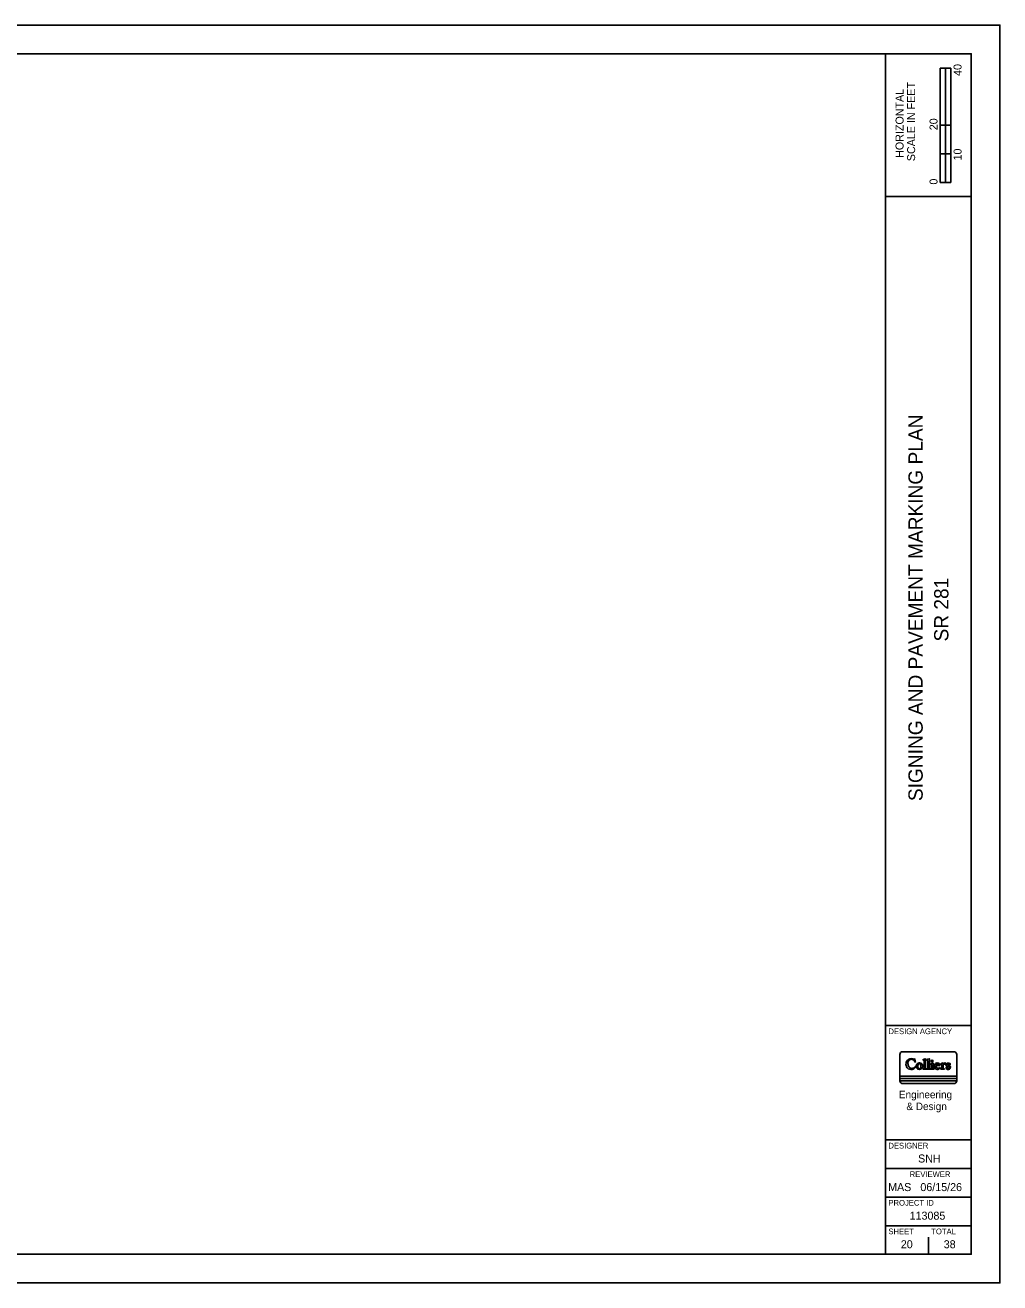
# Model space of a CAD drawing. Extents: x -0.1 to 34, y 0 to 22.
# Drawn here: x 16.94 to 34, y 0 to 22 of the extents above; entities that cross this region are included whole.
import ezdxf

# ---------------------------------------------------------------- set-up
doc = ezdxf.new("R2010")
doc.units = 0
for name, color, linetype in [('SH_Border', 7, 'Continuous'), ('SH_Cut_Line', 7, 'Continuous'), ('SH_Data', 7, 'Continuous'), ('SH_Text', 7, 'Continuous')]:
    doc.layers.add(name, color=color, linetype=linetype)

msp = doc.modelspace()

# ---------------------------------------------------------------- linework, layer by layer
at = {"layer": 'SH_Border'}
for p, q in [((32, 0.5), (32, 21.5)), ((32, 19), (33.5, 19)), ((32, 4.5), (33.5, 4.5)), ((32, 2.5), (33.5, 2.5)), ((32, 2), (33.5, 2)), ((32, 1.5), (33.5, 1.5)), ((32, 1), (33.5, 1))]:
    msp.add_line(p, q, dxfattribs=at)
msp.add_lwpolyline([(1.5, 21.5), (33.5, 21.5), (33.5, 0.5), (1.5, 0.5)], close=True, dxfattribs=at)
at = {"layer": 'SH_Cut_Line'}
msp.add_lwpolyline([(0, 0), (34, 0), (34, 22), (0, 22)], close=True, dxfattribs=at)
at = {"layer": 'SH_Data'}
for p, q in [((32.957, 19.25), (32.957, 21.25)), ((33.144, 21.25), (32.957, 21.25)), ((32.957, 20.25), (32.957, 21.25)), ((32.957, 21.25), (33.05, 21.25)), ((33.05, 21.25), (33.051, 21.25)), ((33.051, 21.25), (33.051, 20.25)), ((33.144, 21.25), (33.144, 19.25)), ((33.051, 20.25), (32.957, 20.25)), ((33.143, 20.25), (33.05, 20.25)), ((33.05, 20.25), (33.05, 19.75)), ((33.143, 19.75), (33.143, 20.25)), ((33.05, 19.75), (32.957, 19.75)), ((32.957, 19.75), (32.957, 19.25)), ((33.05, 19.25), (33.05, 19.75)), ((33.05, 19.75), (33.143, 19.75)), ((33.144, 19.25), (32.957, 19.25)), ((32.957, 19.25), (33.05, 19.25)), ((32.75, 3.5), (32.75, 3.5)), ((32.375, 0.675), (32.375, 0.675)), ((32.75, 0.5), (32.75, 0.8))]:
    msp.add_line(p, q, dxfattribs=at)
at = {"layer": 'SH_Text'}
for p, q in [((33.195, 4.043), (32.299, 4.043)), ((32.506, 3.913), (32.507, 3.91)), ((32.511, 3.864), (32.513, 3.859)), ((32.518, 3.765), (32.522, 3.77)), ((32.596, 3.846), (32.59, 3.846)), ((32.667, 3.745), (32.658, 3.745)), ((32.674, 3.881), (32.674, 3.753)), ((32.701, 3.752), (32.701, 3.916)), ((32.734, 3.745), (32.707, 3.745)), ((32.741, 3.879), (32.741, 3.751)), ((32.768, 3.751), (32.768, 3.916)), ((32.799, 3.745), (32.774, 3.745)), ((32.827, 3.846), (32.791, 3.832)), ((32.805, 3.812), (32.805, 3.751)), ((32.832, 3.749), (32.832, 3.843)), ((32.845, 3.745), (32.836, 3.745)), ((32.886, 3.802), (32.947, 3.802)), ((32.919, 3.81), (32.887, 3.81)), ((32.975, 3.745), (32.968, 3.745)), ((33, 3.846), (32.969, 3.831)), ((32.969, 3.825), (32.976, 3.821)), ((32.982, 3.81), (32.982, 3.753)), ((33.007, 3.828), (33.006, 3.843)), ((33.01, 3.753), (33.01, 3.807)), ((33.026, 3.745), (33.017, 3.745)), ((33.11, 3.833), (33.125, 3.816)), ((33.132, 3.82), (33.13, 3.835)), ((32.249, 3.533), (33.244, 3.533)), ((33.244, 3.533), (32.249, 3.533)), ((32.658, 3.737), (32.845, 3.737)), ((32.968, 3.737), (33.026, 3.737)), ((33.245, 3.535), (33.245, 3.575)), ((32.299, 3.485), (33.195, 3.485))]:
    msp.add_line(p, q, dxfattribs=at)
for points in [[(32.249, 3.993), (32.249, 3.617), (33.245, 3.617), (33.245, 3.993)], [(32.521, 3.861), (32.516, 3.886), (32.514, 3.914)], [(33.245, 3.575), (32.249, 3.575), (32.249, 3.535)]]:
    msp.add_lwpolyline(points, dxfattribs=at)
msp.add_lwpolyline([(33.245, 3.617), (32.249, 3.617), (32.249, 3.575), (33.245, 3.575)], close=True, dxfattribs=at)
msp.add_circle((32.815, 3.879), 0.0155, dxfattribs=at)
for centre, radius, start, end in [((32.299, 3.993), 0.0498, 90, 180), ((33.195, 3.993), 0.0498, 0, 90), ((32.456, 3.826), 0.0996, 122.7772, 219.4331), ((32.445, 3.817), 0.0857, 219.4331, 285.3506), ((32.526, 3.843), 0.135, 175.9543, 206.5569), ((32.457, 3.848), 0.0652, 110.6135, 175.9543), ((32.45, 3.835), 0.0884, 54.7696, 122.7772), ((32.458, 3.81), 0.059, 206.5569, 271.2175), ((32.45, 3.867), 0.0454, 67.8997, 110.6135), ((32.458, 3.828), 0.0773, 271.2175, 317.7042), ((32.437, 3.835), 0.0794, 21.2674, 67.8997), ((32.44, 3.834), 0.104, 285.3506, 318.3029), ((32.503, 3.91), 0.00381, 234.7696, 0.2433), ((32.51, 3.914), 0.00392, 10.93, 183.8175), ((32.516, 3.862), 0.00427, 213.048, 354.7379), ((32.518, 3.773), 0.00456, 317.5815, 137.7042), ((32.594, 3.79), 0.0573, 155.0154, 195.9836), ((32.593, 3.79), 0.0568, 195.9836, 247.4134), ((32.591, 3.791), 0.0549, 91.4708, 155.0154), ((32.627, 3.79), 0.0628, 159.8672, 197.1421), ((32.617, 3.787), 0.0527, 197.1421, 229.9048), ((32.613, 3.795), 0.0485, 128.4847, 159.8672), ((32.592, 3.822), 0.0143, 51.5153, 128.4847), ((32.593, 3.759), 0.0157, 229.9048, 310.0952), ((32.596, 3.791), 0.0547, 22.5432, 90), ((32.572, 3.797), 0.0457, 8.6045, 51.5153), ((32.573, 3.782), 0.0463, 311.5123, 356.3189), ((32.586, 3.797), 0.0652, 292.5866, 340.2533), ((32.532, 3.787), 0.0872, 354.2931, 11.1311), ((32.599, 3.792), 0.0508, 340.2533, 22.5432), ((32.657, 3.901), 0.00323, 122.5943, 271.3615), ((32.658, 3.741), 0.00412, 90, 270), ((32.544, 4.221), 0.336, 289.2258, 296.5694), ((32.657, 3.881), 0.0166, 0, 91.3615), ((32.667, 3.752), 0.00695, 270, 7.6881), ((32.696, 3.916), 0.00466, 0.7043, 112.8976), ((32.709, 3.752), 0.00806, 180, 256.9766), ((32.724, 3.902), 0.00377, 108.5217, 257.147), ((32.641, 4.168), 0.275, 287.2899, 295.7863), ((32.722, 3.879), 0.019, 0, 85.065), ((32.734, 3.751), 0.0065, 270, 3.1556), ((32.763, 3.916), 0.00504, 3.9002, 114.2106), ((32.775, 3.751), 0.00652, 179.2506, 264.6402), ((32.794, 3.829), 0.00399, 126.9098, 263.7558), ((32.792, 3.812), 0.0128, 0, 83.7558), ((32.799, 3.75), 0.00532, 270, 12.3402), ((32.829, 3.843), 0.00324, 356.2318, 111.3032), ((32.837, 3.749), 0.00485, 180, 266.7746), ((32.845, 3.741), 0.00381, 270, 90), ((32.936, 3.789), 0.0786, 158.9201, 196.7689), ((32.904, 3.78), 0.0455, 196.7689, 259.4625), ((32.906, 3.801), 0.0468, 107.3884, 158.9201), ((32.928, 3.794), 0.0459, 174.8749, 230.9242), ((32.886, 3.798), 0.00367, 90, 174.8749), ((32.917, 3.807), 0.0332, 120.4846, 167.2691), ((32.887, 3.813), 0.00338, 167.2691, 270), ((32.909, 3.792), 0.0557, 72.6116, 107.3884), ((32.906, 3.79), 0.0563, 259.4625, 329.9587), ((32.92, 3.784), 0.0321, 230.9242, 328.1623), ((32.907, 3.823), 0.0144, 42.3189, 120.4846), ((32.901, 3.817), 0.0231, 354.1231, 42.3189), ((32.918, 3.815), 0.00543, 277.2594, 354.1231), ((32.914, 3.809), 0.0381, 357.2625, 72.6116), ((32.946, 3.807), 0.00555, 272.7564, 357.2625), ((32.951, 3.764), 0.00454, 329.9587, 148.1623), ((32.968, 3.741), 0.00381, 91.0116, 270), ((32.971, 3.828), 0.0034, 121.2415, 241.2505), ((32.975, 3.752), 0.00704, 270, 9.7141), ((32.969, 3.81), 0.0136, 0, 59.7444), ((33.002, 3.843), 0.00375, 6.4513, 116.174), ((33.009, 3.828), 0.00158, 185.3907, 323.4477), ((33.094, 3.765), 0.104, 130.2856, 143.4477), ((33.033, 3.807), 0.0235, 141.4263, 180.0327), ((33.018, 3.752), 0.00796, 179.3196, 263.9925), ((33.023, 3.815), 0.0105, 58.8554, 141.4263), ((33.038, 3.831), 0.0179, 49.7144, 130.2856), ((33.026, 3.741), 0.00381, 270, 90), ((33.038, 3.839), 0.018, 238.8554, 310.2856), ((33.041, 3.835), 0.0124, 310.2856, 49.7144), ((33.093, 3.812), 0.0332, 143.4089, 199.3264), ((33.065, 3.768), 0.00485, 20.4198, 193.2731), ((32.948, 3.74), 0.116, 4.8826, 13.2731), ((33.087, 3.81), 0.0263, 199.3264, 242.7351), ((33.077, 3.751), 0.014, 184.8826, 242.2064), ((33.093, 3.812), 0.0334, 105.6066, 143.4089), ((33.118, 3.787), 0.0516, 200.4198, 231.7135), ((33.093, 3.782), 0.0486, 242.2064, 319.0024), ((33.141, 3.915), 0.144, 242.7351, 255.1442), ((33.093, 3.822), 0.0133, 123.6114, 236.3886), ((33.099, 3.79), 0.0558, 61.5074, 105.6066), ((33.099, 3.813), 0.0238, 78.1441, 123.6114), ((33.111, 3.85), 0.0468, 236.3886, 262.0524), ((33.098, 3.761), 0.0185, 231.7135, 325.4966), ((33.101, 3.825), 0.0115, 42.5173, 78.1441), ((33.1, 3.76), 0.016, 325.4966, 75.1442), ((33.099, 3.763), 0.0407, 40.9976, 82.0524), ((33.128, 3.819), 0.00433, 219.7222, 9.1323), ((33.122, 3.833), 0.00795, 16.8946, 61.5074), ((33.107, 3.77), 0.0305, 319.0024, 40.9976), ((32.299, 3.535), 0.0498, 180, 183.1495), ((32.299, 3.535), 0.0498, 183.1495, 270), ((32.591, 3.784), 0.0512, 247.4134, 292.5866), ((33.195, 3.535), 0.0498, 270, 356.8505), ((33.195, 3.535), 0.0498, 356.8505, 0)]:
    msp.add_arc(centre, radius, start, end, dxfattribs=at)

# ---------------------------------------------------------------- texts
at = {"layer": 'SH_Data'}
for s, height, p in [('40', 0.14, (33.33, 21.112)), ('SCALE IN FEET', 0.14, (32.517, 19.621)), ('HORIZONTAL', 0.14, (32.315, 19.679)), ('20', 0.14, (32.91, 20.162)), ('10', 0.14, (33.33, 19.633)), ('0', 0.14, (32.91, 19.211)), ('SIGNING AND PAVEMENT MARKING PLAN', 0.25, (32.65, 8.427)), ('SR 281', 0.25, (33.1, 11.219))]:
    msp.add_text(s, height=height, rotation=90, dxfattribs=at).set_placement(p)
for s, height, p in [('DESIGN AGENCY', 0.1, (32.05, 4.35)), ('DESIGNER', 0.1, (32.05, 2.35)), ('SNH', 0.14, (32.569, 2.105)), ('REVIEWER', 0.1, (32.422, 1.85)), ('MAS', 0.14, (32.045, 1.605)), ('06/15/26', 0.14, (32.609, 1.605)), ('PROJECT ID', 0.1, (32.05, 1.35)), ('113085', 0.14, (32.421, 1.105)), ('SHEET', 0.1, (32.05, 0.85)), ('TOTAL', 0.1, (32.8, 0.85)), ('20', 0.14, (32.267, 0.605)), ('38', 0.14, (33.018, 0.605))]:
    msp.add_text(s, height=height, dxfattribs=at).set_placement(p)
at = {"layer": 'SH_Text'}
for s, height, p in [('Engineering', 0.13025, (32.234, 3.229)), ('& Design', 0.1303, (32.365, 3.022))]:
    msp.add_text(s, height=height, dxfattribs=at).set_placement(p)

doc.saveas('drawing.dxf')
